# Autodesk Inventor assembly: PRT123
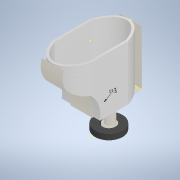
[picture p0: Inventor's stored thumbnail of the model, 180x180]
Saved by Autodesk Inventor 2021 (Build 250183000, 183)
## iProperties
Created: 2023-08
Part Number: PRT123
Document SubType Name: Assembly
Designer: Isaac M Iker C
Author: Isaac M Iker C
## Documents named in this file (4)
- C:\Users\canad\Documents\ULACIT\Mecanica\Proyecto\Assembly1.iam
- C:\Users\canad\Documents\ULACIT\Mecanica\Proyecto\Part1.ipt
- C:\Users\canad\Documents\ULACIT\Mecanica\Proyecto\Part2.ipt
- C:\Users\canad\Documents\ULACIT\Mecanica\Proyecto\Part3.ipt
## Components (3 placed, 3 different names)
1. Part1:1
2. Part2:1
3. Part3:1
